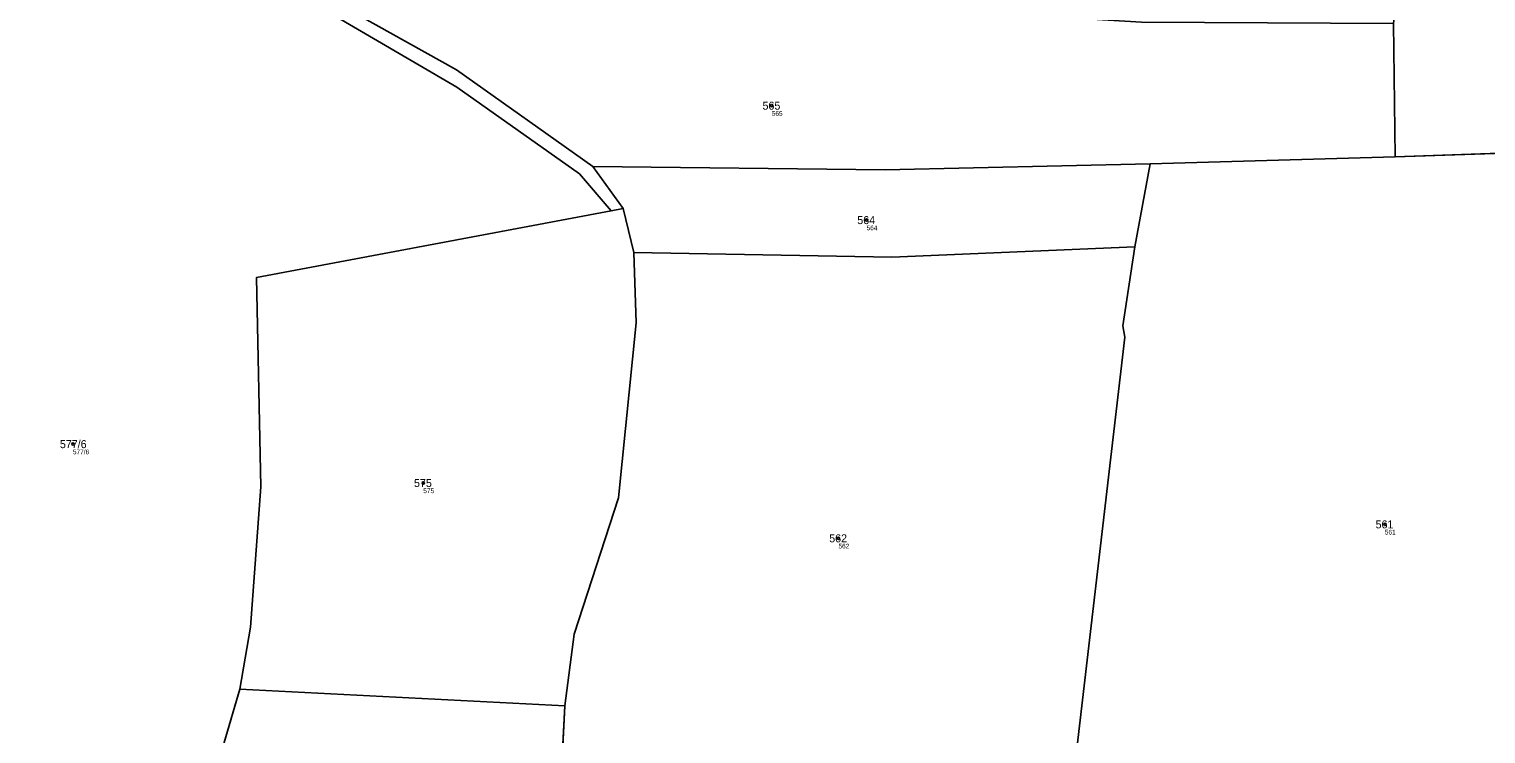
# Model space of a CAD drawing. Extents: x -767985 to -763816, y -1059600 to -1057360.
# Drawn here: x -764545.8 to -764236.2, y -1059117.3 to -1058967.5 of the extents above; entities that cross this region are included whole.
import ezdxf

# ---------------------------------------------------------------- set-up
doc = ezdxf.new("R2010")
doc.units = 0
for name, color, linetype in [('Definiční body', 7, 'Continuous'), ('Hranice parcel', 7, 'Continuous'), ('Parcelní čísla', 7, 'Continuous'), ('Polygon parcely', 7, 'Continuous')]:
    doc.layers.add(name, color=color, linetype=linetype)

msp = doc.modelspace()

# ---------------------------------------------------------------- linework, layer by layer
at = {"layer": 'Definiční body'}
for centre in [(-764387.96, -1058983.72994), (-764367.82, -1059008.05994), (-764536.46, -1059055.68994), (-764462.01, -1059063.94994), (-764257.7, -1059072.74994), (-764373.79, -1059075.70994)]:
    msp.add_circle(centre, 0.25, dxfattribs=at)
at = {"layer": 'Hranice parcel'}
for p, q in [((-764255.86, -1058966.23), (-764255.54, -1058994.61)), ((-764255.54, -1058994.61), (-764215.38, -1058993.24)), ((-764426.01, -1058996.65), (-764419.54, -1059005.59)), ((-764307.58, -1058996.13), (-764310.82, -1059013.77)), ((-764255.54, -1058994.61), (-764307.58, -1058996.13)), ((-764419.54, -1059005.59), (-764422.1, -1059006.07)), ((-764419.54, -1059005.59), (-764417.28, -1059014.98)), ((-764500.98, -1059107.77), (-764431.95, -1059111.35)), ((-764431.95, -1059111.35), (-764433.32, -1059138.58))]:
    msp.add_line(p, q, dxfattribs=at)
for points in [[(-764422.1, -1059006.07), (-764428.85, -1058998.23), (-764454.9, -1058979.8), (-764483.17, -1058963.28), (-764516.36, -1058954.39), (-764534.62, -1058947.71), (-764550.97, -1058937.86)], [(-764510.68, -1058952.79), (-764482.48, -1058960.66), (-764454.96, -1058976.1), (-764426.01, -1058996.65)], [(-764307.58, -1058996.13), (-764363.85, -1058997.35), (-764426.01, -1058996.65)], [(-764422.1, -1059006.07), (-764497.42, -1059020.24), (-764496.53, -1059064.78), (-764498.75, -1059094.63), (-764500.98, -1059107.77)], [(-764417.28, -1059014.98), (-764416.78, -1059029.9), (-764420.51, -1059067.08), (-764429.96, -1059096.06), (-764431.95, -1059111.35)], [(-764310.82, -1059013.77), (-764362.47, -1059015.92), (-764417.28, -1059014.98)], [(-764310.82, -1059013.77), (-764313.4, -1059030.55), (-764312.97, -1059032.98), (-764324.44, -1059131.35)], [(-764500.98, -1059107.77), (-764504.32, -1059119.13), (-764507.61, -1059139.04)]]:
    msp.add_lwpolyline(points, dxfattribs=at)
at = {"layer": 'Polygon parcely'}
for points in [[(-764133.76, -1058962.77), (-764131.29, -1058923.53), (-764129.55, -1058895.82), (-764246.31, -1058873.43), (-764255.86, -1058966.23), (-764255.54, -1058994.61), (-764215.38, -1058993.24), (-764138.31, -1058991.9)], [(-764647.72, -1058896.12), (-764600.3, -1058914.3), (-764550.97, -1058937.86), (-764534.62, -1058947.71), (-764516.36, -1058954.39), (-764483.17, -1058963.28), (-764454.9, -1058979.8), (-764428.85, -1058998.23), (-764422.1, -1059006.07), (-764419.54, -1059005.59), (-764426.01, -1058996.65), (-764454.96, -1058976.1), (-764482.48, -1058960.66), (-764510.68, -1058952.79), (-764533.08, -1058945.22), (-764554.5, -1058931.66), (-764602.1, -1058910.08), (-764647.54, -1058894.05)], [(-764385.95, -1058958.19), (-764415.5, -1058952.65), (-764506.78, -1058934.04), (-764510.68, -1058952.79), (-764482.48, -1058960.66), (-764454.96, -1058976.1), (-764426.01, -1058996.65), (-764363.85, -1058997.35), (-764307.58, -1058996.13), (-764255.54, -1058994.61), (-764255.86, -1058966.23), (-764309.43, -1058965.95), (-764341.31, -1058964.1), (-764365.33, -1058961.14)], [(-764573.5, -1059077.29), (-764572, -1059077.35), (-764574.27, -1059110.44), (-764575.79, -1059132.56), (-764553.86, -1059135.67), (-764528.62, -1059138.32), (-764507.61, -1059139.04), (-764504.32, -1059119.13), (-764500.98, -1059107.77), (-764498.75, -1059094.63), (-764496.53, -1059064.78), (-764497.42, -1059020.24), (-764422.1, -1059006.07), (-764428.85, -1058998.23), (-764454.9, -1058979.8), (-764483.17, -1058963.28), (-764516.36, -1058954.39), (-764534.62, -1058947.71), (-764550.97, -1058937.86), (-764553.99, -1058960.4), (-764565.74, -1058995.14), (-764571.94, -1059044.52)], [(-764064.7, -1059102.28), (-764059.67, -1059077.89), (-764105.35, -1059075.54), (-764175.95, -1059061.87), (-764220.51, -1059056.43), (-764216.77, -1059022.53), (-764215.38, -1058993.24), (-764255.54, -1058994.61), (-764307.58, -1058996.13), (-764310.82, -1059013.77), (-764313.4, -1059030.55), (-764312.97, -1059032.98), (-764324.44, -1059131.35), (-764322.82, -1059131.2), (-764299.07, -1059129.05), (-764241.76, -1059123.87), (-764182.19, -1059110.29), (-764135.19, -1059117.33), (-764122.02, -1059102.59)], [(-764363.85, -1058997.35), (-764426.01, -1058996.65), (-764419.54, -1059005.59), (-764417.28, -1059014.98), (-764362.47, -1059015.92), (-764310.82, -1059013.77), (-764307.58, -1058996.13)], [(-764500.98, -1059107.77), (-764431.95, -1059111.35), (-764429.96, -1059096.06), (-764420.51, -1059067.08), (-764416.78, -1059029.9), (-764417.28, -1059014.98), (-764419.54, -1059005.59), (-764422.1, -1059006.07), (-764497.42, -1059020.24), (-764496.53, -1059064.78), (-764498.75, -1059094.63)], [(-764310.82, -1059013.77), (-764362.47, -1059015.92), (-764417.28, -1059014.98), (-764416.78, -1059029.9), (-764420.51, -1059067.08), (-764429.96, -1059096.06), (-764431.95, -1059111.35), (-764433.32, -1059138.58), (-764367.81, -1059134.6), (-764346.04, -1059132.97), (-764324.44, -1059131.35), (-764312.97, -1059032.98), (-764313.4, -1059030.55)], [(-764502.49, -1059139.01), (-764482.49, -1059138.88), (-764433.32, -1059138.58), (-764431.95, -1059111.35), (-764500.98, -1059107.77), (-764504.32, -1059119.13), (-764507.61, -1059139.04)]]:
    msp.add_lwpolyline(points, close=True, dxfattribs=at)

# ---------------------------------------------------------------- texts
at = {"layer": 'Definiční body'}
for s, p in [('565', (-764387.96, -1058985.886)), ('564', (-764367.82, -1059010.216)), ('577/6', (-764536.46, -1059057.846)), ('575', (-764462.01, -1059066.106)), ('561', (-764257.7, -1059074.906)), ('562', (-764373.79, -1059077.866))]:
    msp.add_text(s, height=0.999996, dxfattribs=at).set_placement(p)
at = {"layer": 'Parcelní čísla'}
for s, p in [('565', (-764389.934, -1058984.58)), ('564', (-764369.794, -1059008.91)), ('577/6', (-764539.233, -1059056.54)), ('575', (-764463.984, -1059064.8)), ('561', (-764259.674, -1059073.6)), ('562', (-764375.764, -1059076.56))]:
    msp.add_text(s, height=1.699998, dxfattribs=at).set_placement(p)

doc.saveas('drawing.dxf')
